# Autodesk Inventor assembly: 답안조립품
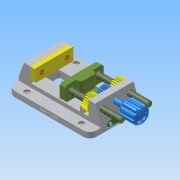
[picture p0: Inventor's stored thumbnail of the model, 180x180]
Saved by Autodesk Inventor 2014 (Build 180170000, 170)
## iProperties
Created: 2018-03
Part Number: 답안조립품
Document SubType Name: Assembly
Designer: user
Author: user
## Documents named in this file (10)
- C:\Users\user\Desktop\380307V1008\답안조립품.iam
- C:\Users\user\Desktop\380307V1008\바이스본체 A.ipt
- C:\Users\user\Desktop\380307V1008\바이스본체 B.ipt
- C:\Users\user\Desktop\380307V1008\고정 플레이트.ipt
- C:\Users\user\Desktop\380307V1008\지지대.ipt
- C:\Users\user\Desktop\380307V1008\슬라이딩 부품.ipt
- C:\Users\user\Desktop\380307V1008\스퍼기어.ipt
- C:\Users\user\Desktop\380307V1008\핸들.ipt
- C:\Users\user\Desktop\380307V1008\십자오목머리나사 M3.ipt
- C:\Users\user\Desktop\380307V1008\십자오목머리나사 M4.ipt
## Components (3 placed, 2 different names)
1. 고정 플레이트:1
2. 고정 플레이트:2
3. 핸들:1 — 각도:1
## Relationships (1: Angle 1)
- 각도:1 [Angle]: 핸들:1
